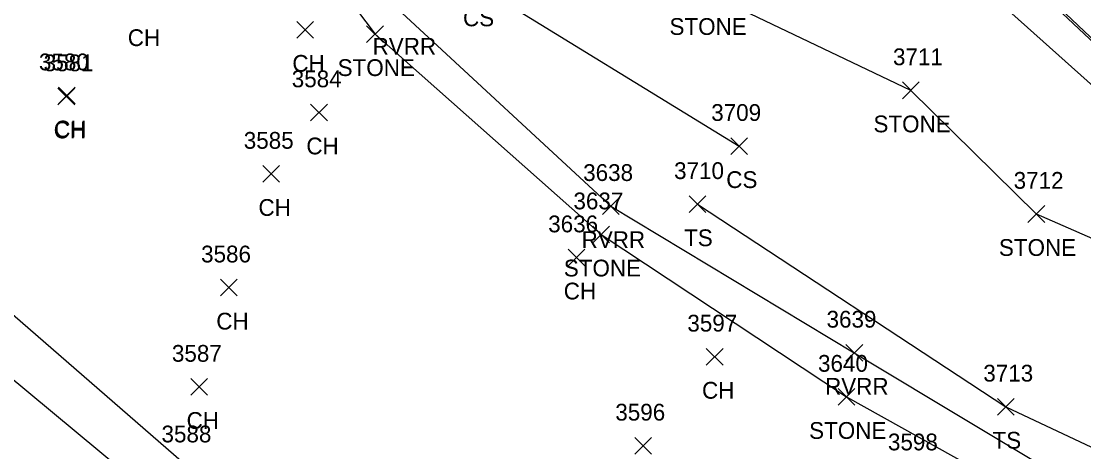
# Model space of a CAD drawing. Extents: x 1647574 to 1652703, y 212895 to 228670.
# Drawn here: x 1648544.2 to 1648670.8, y 227337.9 to 227389.2 of the extents above; entities that cross this region are included whole.
import ezdxf

# ---------------------------------------------------------------- set-up
doc = ezdxf.new("R2010")
doc.units = 0
for name, color, linetype in [('BDC', 7, 'Continuous'), ('L_A', 7, 'Continuous'), ('L_I', 7, 'Continuous'), ('L_TIC', 7, 'Continuous'), ('LASF', 7, 'Continuous'), ('LAWE', 7, 'Continuous'), ('LELB', 7, 'Continuous')]:
    doc.layers.add(name, color=color, linetype=linetype)

msp = doc.modelspace()

# ---------------------------------------------------------------- linework, layer by layer
at = {"layer": 'BDC'}
for points in [[(1648650.62, 227406.77), (1648690.52, 227369.25), (1648733.47, 227328.73), (1648776.31, 227288.32), (1648833.66, 227234.3), (1648891.23, 227180.05), (1648955.86, 227118.96), (1649002.64, 227075.02), (1649045.28, 227034.6)], [(1648651.08, 227406.8), (1648690.74, 227369.26), (1648733.46, 227328.85), (1648776.32, 227288.43), (1648833.71, 227234.41), (1648891.3, 227180.17), (1648955.95, 227119.2), (1649002.81, 227075.03), (1649045.28, 227034.88)]]:
    msp.add_lwpolyline(points, dxfattribs=at)
at = {"layer": 'L_TIC'}
for points in [[(1648577, 227387.18), (1648579, 227389.18)], [(1648579, 227387.18), (1648577, 227389.18)], [(1648585.34, 227386.67), (1648587.34, 227388.67)], [(1648587.34, 227386.67), (1648585.34, 227388.67)], [(1648548.53, 227379.24), (1648550.53, 227381.24)], [(1648550.53, 227379.24), (1648548.53, 227381.24)], [(1648548.6, 227379.35), (1648550.6, 227381.35)], [(1648550.6, 227379.35), (1648548.6, 227381.35)], [(1648649.22, 227379.96), (1648651.22, 227381.96)], [(1648651.22, 227379.96), (1648649.22, 227381.96)], [(1648578.66, 227377.33), (1648580.66, 227379.33)], [(1648580.66, 227377.33), (1648578.66, 227379.33)], [(1648628.77, 227373.32), (1648630.77, 227375.32)], [(1648630.77, 227373.32), (1648628.77, 227375.32)], [(1648572.95, 227370), (1648574.95, 227372)], [(1648574.95, 227370), (1648572.95, 227372)], [(1648613.46, 227366.16), (1648615.46, 227368.16)], [(1648615.46, 227366.16), (1648613.46, 227368.16)], [(1648623.78, 227366.39), (1648625.78, 227368.39)], [(1648625.78, 227366.39), (1648623.78, 227368.39)], [(1648664.19, 227365.23), (1648666.19, 227367.23)], [(1648666.19, 227365.23), (1648664.19, 227367.23)], [(1648612.3, 227362.78), (1648614.3, 227364.78)], [(1648614.3, 227362.78), (1648612.3, 227364.78)], [(1648609.35, 227360.04), (1648611.35, 227362.04)], [(1648611.35, 227360.04), (1648609.35, 227362.04)], [(1648567.92, 227356.45), (1648569.92, 227358.45)], [(1648569.92, 227356.45), (1648567.92, 227358.45)], [(1648642.49, 227348.68), (1648644.49, 227350.68)], [(1648644.49, 227348.68), (1648642.49, 227350.68)], [(1648625.84, 227348.21), (1648627.84, 227350.21)], [(1648627.84, 227348.21), (1648625.84, 227350.21)], [(1648564.38, 227344.61), (1648566.38, 227346.61)], [(1648566.38, 227344.61), (1648564.38, 227346.61)], [(1648641.55, 227343.42), (1648643.55, 227345.42)], [(1648643.55, 227343.42), (1648641.55, 227345.42)], [(1648660.56, 227342.25), (1648662.56, 227344.25)], [(1648662.56, 227342.25), (1648660.56, 227344.25)], [(1648617.31, 227337.6), (1648619.31, 227339.6)], [(1648619.31, 227337.6), (1648617.31, 227339.6)]]:
    msp.add_lwpolyline(points, dxfattribs=at)
at = {"layer": 'LASF'}
for points in [[(1648519.8, 227461.38), (1648554.26, 227428.39), (1648572.41, 227406.15), (1648586.34, 227387.67), (1648613.3, 227363.78), (1648642.55, 227344.42), (1648670.5, 227328.87), (1648696.33, 227320.92)], [(1648650.22, 227380.96), (1648625.91, 227392.57)], [(1648499.8, 227390.79), (1648534.24, 227361.96), (1648564.14, 227336), (1648594.15, 227310.22), (1648628.6, 227293.4), (1648654.27, 227279.63), (1648686.16, 227265.62), (1648717.14, 227256.76), (1648740.63, 227248.95), (1648765.89, 227244.08), (1648814.22, 227231.85), (1648833.28, 227225.74), (1648856.55, 227221.69), (1648882.06, 227215.37), (1648909.35, 227210.97), (1648936.5, 227203.8), (1648961.57, 227198.17), (1648983.3, 227192.86), (1648997.71, 227192.89), (1649002, 227200.33)], [(1648650.22, 227380.96), (1648665.19, 227366.23), (1648704.75, 227348.92), (1648726.24, 227345), (1648748.02, 227340.21), (1648778.69, 227335.47), (1648795.18, 227328.09), (1648829.72, 227323.98), (1648869.23, 227314.25), (1648889.74, 227315.36), (1648906.07, 227312.61), (1648918.66, 227314.37), (1648951.49, 227306.35), (1648977.57, 227292.25), (1648987.29, 227278.61), (1648987.25, 227274.74)]]:
    msp.add_lwpolyline(points, dxfattribs=at)
at = {"layer": 'LAWE'}
for points in [[(1648523.62, 227464.44), (1648558.32, 227431.33), (1648577.14, 227410.1), (1648589.54, 227390.22), (1648614.46, 227367.16), (1648643.49, 227349.68), (1648671.91, 227332.59), (1648697.56, 227323.9), (1648718.58, 227316.22), (1648748.46, 227309.79), (1648786.4, 227302.27), (1648830.69, 227294.49), (1648864.9, 227288.6), (1648895.3, 227284.45), (1648918.11, 227285.91), (1648972.01, 227267.7), (1649004.52, 227260.1), (1649036.33, 227254.75), (1649067.75, 227244.93), (1649099.56, 227239.62), (1649133.34, 227233.56), (1649168.72, 227227.53), (1649200.78, 227221.11), (1649219.75, 227218.74)], [(1648476.38, 227405.22), (1648496.15, 227388.22), (1648530.66, 227356.87), (1648567.87, 227325.98), (1648591.32, 227307.77), (1648628.32, 227290.49), (1648653.2, 227277.3), (1648685.98, 227263.74), (1648715.08, 227253.44), (1648739.53, 227246.57), (1648765.37, 227238.45), (1648812.94, 227227.92), (1648833.65, 227223.23), (1648856.01, 227219.81), (1648882.17, 227213.58), (1648908.49, 227208.96)]]:
    msp.add_lwpolyline(points, dxfattribs=at)
at = {"layer": 'LELB'}
for points in [[(1648522.38, 227469.84), (1648562.61, 227436.01), (1648584.88, 227407.72), (1648598.39, 227393.6), (1648629.77, 227374.32)], [(1648655.91, 227395.86), (1648675, 227378.76), (1648703.41, 227359.47), (1648723.98, 227350.84), (1648755.18, 227345.02), (1648824.56, 227329.56), (1648858.75, 227322.28), (1648879.14, 227320.58)], [(1648624.78, 227367.39), (1648661.56, 227343.25), (1648687.99, 227330.79), (1648710.88, 227324.59), (1648732.4, 227320.11), (1648758.29, 227314.94), (1648781.98, 227308.53), (1648826.95, 227303.5), (1648863.73, 227300.17), (1648907.54, 227292.02), (1648945.17, 227284.73), (1648987.25, 227274.74), (1649006.39, 227273.99), (1649032.82, 227270.54), (1649043.18, 227273.01), (1649036.39, 227297.45)]]:
    msp.add_lwpolyline(points, dxfattribs=at)

# ---------------------------------------------------------------- texts
at = {"layer": 'L_A'}
for s, p in [('CS', (1648596.83, 227388.6)), ('STONE', (1648621.45, 227387.57)), ('CH', (1648556.86, 227386.24)), ('RVRR', (1648586.05, 227385.22)), ('CH', (1648576.48, 227383.18)), ('STONE', (1648581.88, 227382.67)), ('CH', (1648548.02, 227375.24)), ('CH', (1648548.09, 227375.35)), ('STONE', (1648645.77, 227375.96)), ('CH', (1648578.15, 227373.33)), ('CS', (1648628.22, 227369.32)), ('CH', (1648572.44, 227366)), ('TS', (1648623.19, 227362.39)), ('RVRR', (1648610.97, 227362.16)), ('STONE', (1648660.73, 227361.23)), ('STONE', (1648608.85, 227358.78)), ('CH', (1648608.84, 227356.04)), ('CH', (1648567.41, 227352.45)), ('RVRR', (1648640, 227344.68)), ('CH', (1648625.33, 227344.21)), ('CH', (1648563.87, 227340.61)), ('STONE', (1648638.1, 227339.42)), ('TS', (1648659.97, 227338.25))]:
    msp.add_text(s, height=2, dxfattribs=at).set_placement(p)
at = {"layer": 'L_I'}
for s, p in [('3711', (1648648.1, 227383.96)), ('3580', (1648546.26, 227383.35)), ('3581', (1648546.83, 227383.24)), ('3584', (1648576.41, 227381.33)), ('3709', (1648626.43, 227377.32)), ('3585', (1648570.69, 227374)), ('3638', (1648611.16, 227370.16)), ('3710', (1648622, 227370.39)), ('3712', (1648662.49, 227369.23)), ('3637', (1648610, 227366.78)), ('3636', (1648606.99, 227364.04)), ('3586', (1648565.6, 227360.45)), ('3597', (1648623.58, 227352.21)), ('3639', (1648640.18, 227352.68)), ('3587', (1648562.12, 227348.61)), ('3640', (1648639.16, 227347.42)), ('3713', (1648658.87, 227346.25)), ('3596', (1648614.99, 227341.6)), ('3588', (1648560.88, 227339)), ('3598', (1648647.5, 227338.05))]:
    msp.add_text(s, height=2, dxfattribs=at).set_placement(p)

doc.saveas('drawing.dxf')
